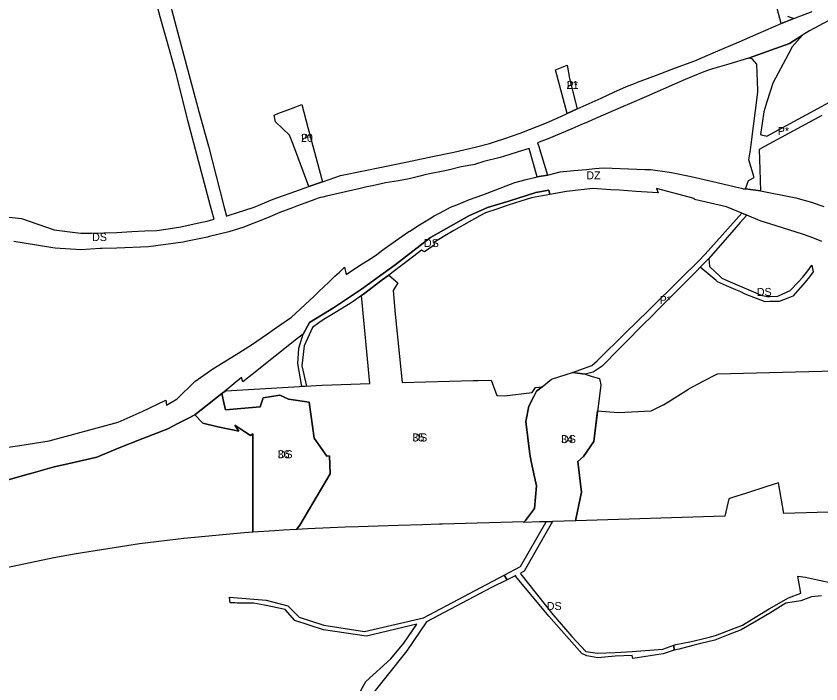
# Model space of a CAD drawing. Extents: x -501732 to -497665, y -1142022 to -1138283.
# Drawn here: x -499525 to -498822, y -1140888 to -1140303 of the extents above; entities that cross this region are included whole.
import ezdxf

# ---------------------------------------------------------------- set-up
doc = ezdxf.new("R2010")
doc.units = 0
for name, color, linetype in [('4', 7, 'Continuous'), ('43', 7, 'Continuous'), ('44', 7, 'Continuous'), ('5', 7, 'Continuous'), ('61', 7, 'Continuous'), ('7', 7, 'Continuous')]:
    doc.layers.add(name, color=color, linetype=linetype)

msp = doc.modelspace()

# ---------------------------------------------------------------- linework, layer by layer
at = {"layer": '4'}
for points in [[(-499533.86, -1140478.84), (-499520.59, -1140480.42), (-499492.05, -1140490.24), (-499471.17, -1140493.01), (-499468.63, -1140493.35), (-499459.42, -1140493.11), (-499448.67, -1140492.82), (-499437.1, -1140492.61), (-499424.11, -1140491.92), (-499412.75, -1140491.32), (-499402.08, -1140490.76), (-499392.35, -1140489.33), (-499381.33, -1140487.71), (-499369.64, -1140485.14), (-499357.43, -1140482.45), (-499354.19, -1140481.62), (-499352.11, -1140481.09), (-499355.18, -1140469.543), (-499375.07, -1140394.73), (-499384.85, -1140355.82), (-499390.45, -1140334.96), (-499399.25, -1140304.07), (-499413.21, -1140251.05)], [(-499391.39, -1140289.65), (-499381.85, -1140325.93), (-499365.33, -1140386.89), (-499357.13, -1140417.19), (-499343.61, -1140469.6), (-499341.31, -1140478.34), (-499339.68, -1140477.92), (-499317.1, -1140470.61), (-499300.46, -1140463.58), (-499281.61, -1140456.77), (-499269.37, -1140452.35), (-499266.71, -1140451.48), (-499264.81, -1140450.86), (-499263.54, -1140450.42), (-499257.33, -1140448.28), (-499256.34, -1140447.94), (-499241.58, -1140442.84), (-499221.53, -1140438.73), (-499204.27, -1140435.21), (-499202.74, -1140434.9), (-499184.51, -1140431.25), (-499165.12, -1140427.13), (-499161.13, -1140426.28), (-499142.43, -1140422.43), (-499123.87, -1140417.86), (-499111.16, -1140414.8), (-499105.974, -1140413.043), (-499097.94, -1140410.32), (-499084.44, -1140405.81), (-499061.44, -1140396.85), (-499048.96, -1140391.13), (-499043.27, -1140388.5), (-499034.63, -1140384.57), (-499013.75, -1140375), (-499002.59, -1140369.89), (-498991.5, -1140364.81), (-498984.65, -1140362.16), (-498981.92, -1140361.11), (-498965.17, -1140354.88), (-498948.6, -1140348.71), (-498931.83, -1140342.49), (-498913.6, -1140334.63), (-498892.94, -1140325.78), (-498876.36, -1140318.59), (-498856.22, -1140309.93), (-498852.4, -1140308.48), (-498845.2, -1140305.46), (-498829.21, -1140299.26)], [(-498815.24, -1140307.37), (-498831.5, -1140316.35), (-498835.82, -1140318.73), (-498837.51, -1140319.95), (-498849.08, -1140327.24), (-498884.91, -1140340.06), (-498901.89, -1140345.34), (-498916.42, -1140349.39), (-498919.84, -1140350.56), (-498923.98, -1140351.97), (-498928.75, -1140354.01), (-498940.1, -1140358.86), (-498949.62, -1140363), (-498959.42, -1140367.18), (-498973.97, -1140373.54), (-498988.97, -1140379.94), (-498994.37, -1140382.35), (-499018.51, -1140392.91), (-499025.04, -1140395.74), (-499031.55, -1140398.55), (-499039.4, -1140401.93), (-499059.29, -1140410.28), (-499069.33, -1140414.16), (-499069.02, -1140415.15), (-499068.57, -1140416.62), (-499060.61, -1140442.4), (-499069.49, -1140443.83), (-499076.68, -1140419.16), (-499086.13, -1140422.11), (-499094.46, -1140424.71), (-499102.1, -1140427.1), (-499116.22, -1140430.62), (-499123.5, -1140432.96), (-499124.06, -1140433.14), (-499135.95, -1140435.12), (-499147.59, -1140438.06), (-499153.2, -1140439.37), (-499162.17, -1140441.11), (-499167.85, -1140442.22), (-499172.15, -1140443.33), (-499181.49, -1140445.74), (-499190.84, -1140447.37), (-499202.11, -1140449.32), (-499213.64, -1140451.77), (-499218.43, -1140452.79), (-499224.48, -1140454.07), (-499237.22, -1140457.01), (-499253.91, -1140460.9), (-499256.93, -1140461.6), (-499259, -1140462.08), (-499261.13, -1140462.58), (-499264.09, -1140463.7), (-499272.833, -1140467.006), (-499279.11, -1140469.38), (-499283.56, -1140471.07), (-499294.72, -1140475.29), (-499303.43, -1140478.89), (-499312.68, -1140482.72), (-499319.8, -1140485.44), (-499326.12, -1140487.86), (-499339.19, -1140492.06), (-499356.17, -1140496.24), (-499357.15, -1140496.44), (-499357.988, -1140496.615), (-499376.73, -1140500.52), (-499379.3, -1140501.05), (-499403.15, -1140504.27), (-499409.47, -1140505.06), (-499437.13, -1140506.39), (-499450.1, -1140506.6), (-499451.64, -1140506.71), (-499468.57, -1140507.86), (-499491.14, -1140506.29), (-499493.22, -1140506.15), (-499496.6, -1140505.58), (-499527.13, -1140500.39)]]:
    msp.add_lwpolyline(points, dxfattribs=at)
for points in [[(-499159.55, -1140503.7), (-499168.02, -1140509.43), (-499170.64, -1140508.17), (-499177.54, -1140513.37), (-499189.52, -1140522.4), (-499199.435, -1140529.871), (-499200.19, -1140530.44), (-499205.05, -1140534.1), (-499209.99, -1140537.82), (-499220.46, -1140545.72), (-499223.155, -1140547.686), (-499230.66, -1140553.16), (-499233.16, -1140554.69), (-499236.04, -1140556.46), (-499241.25, -1140559.66), (-499246.66, -1140562.99), (-499251.02, -1140565.67), (-499255.78, -1140568.6), (-499260.6, -1140571.56), (-499266.099, -1140575.67), (-499273.423, -1140591.91), (-499275.476, -1140609.215), (-499271.445, -1140627.037), (-499275.262, -1140627.268), (-499278.996, -1140607.162), (-499278.116, -1140593.963), (-499274.18, -1140581.709), (-499268.73, -1140571.377), (-499247.611, -1140558.471), (-499223.265, -1140542.339), (-499193.933, -1140520.926), (-499162.842, -1140497.167), (-499129.403, -1140478.102), (-499112.977, -1140470.769), (-499093.618, -1140464.902), (-499070.739, -1140457.569), (-499059.3, -1140455.516), (-499058.422, -1140459.318), (-499074.55, -1140462.3), (-499083.99, -1140465.33), (-499094.87, -1140468.82), (-499105.77, -1140472.44), (-499114.75, -1140475.43), (-499119.674, -1140478.143), (-499129.23, -1140483.41), (-499142.57, -1140490.76), (-499150.34, -1140495.5), (-499155.56, -1140498.69), (-499159.98, -1140501.39)], [(-498866.028, -1140548.575), (-498859.16, -1140548.39), (-498855.36, -1140546.65), (-498848.48, -1140543.51), (-498841.42, -1140536.07), (-498837.56, -1140532), (-498833.07, -1140526.12), (-498829.33, -1140521.23), (-498828.23, -1140527.09), (-498831.44, -1140531.44), (-498835.39, -1140536.01), (-498846.01, -1140548.29), (-498850.51, -1140550.01), (-498858.03, -1140552.89), (-498866.08, -1140553.12), (-498870.24, -1140553.24), (-498887.81, -1140546.48), (-498891.52, -1140544.61), (-498896.02, -1140542.85), (-498903.99, -1140539.28), (-498911.91, -1140535.74), (-498913.17, -1140534.68), (-498927.07, -1140523.04), (-498919.49, -1140515.35), (-498918.88, -1140522.32), (-498910.03, -1140530.82), (-498908.07, -1140532.7), (-498900.87, -1140535.83), (-498874.38, -1140547.33), (-498872.65, -1140547.69), (-498868.09, -1140548.63)], [(-499061.682, -1140745.688), (-499056.3, -1140745.482), (-499080.97, -1140788.98), (-499084.32, -1140790.665), (-499083.85, -1140791.45), (-499055.84, -1140826.78), (-499039.41, -1140846.13), (-499027.17, -1140859.16), (-499016.91, -1140860.81), (-499001.5, -1140859.99), (-498986.43, -1140859.19), (-498959.73, -1140857.26), (-498950.11, -1140853.73), (-498950.06, -1140853.98), (-498949.88, -1140858.17), (-498959.32, -1140861.25), (-498986.02, -1140865.45), (-498986.43, -1140862.59), (-499001.47, -1140863.31), (-499016.46, -1140864.79), (-499026.07, -1140862.91), (-499030.49, -1140860.96), (-499059.43, -1140828.31), (-499088.14, -1140793.58), (-499088.374, -1140792.704), (-499095.98, -1140796.53), (-499098.45, -1140792.47), (-499084.18, -1140784.93)]]:
    msp.add_lwpolyline(points, close=True, dxfattribs=at)
at = {"layer": '43'}
for points in [[(-498850.81, -1140303.29), (-498845.2, -1140305.46), (-498852.4, -1140308.48), (-498856.22, -1140309.93), (-498862.32, -1140286.49)], [(-498820.71, -1140390.17), (-498838.52, -1140399.91), (-498856.24, -1140409.61), (-498870.72, -1140417.49), (-498875.59, -1140420.12), (-498874.91, -1140437.43), (-498874.22, -1140456.1), (-498887.5, -1140454.53), (-498884.7, -1140447.25), (-498879.75, -1140444.45), (-498884.45, -1140429), (-498883.12, -1140420.33), (-498882.38, -1140415.55), (-498876.66, -1140369.91), (-498876.72, -1140368.25), (-498877.56, -1140345.24), (-498881.63, -1140340.74), (-498884.91, -1140340.06), (-498849.08, -1140327.24), (-498837.51, -1140319.95), (-498846.62, -1140330.16), (-498849.91, -1140336.39), (-498863.6, -1140362.01), (-498865.87, -1140369.32), (-498868.67, -1140378.34), (-498871.39, -1140387.11), (-498874.37, -1140406.98), (-498872.69, -1140407.39), (-498869.69, -1140408.13), (-498868.81, -1140408.5), (-498824.33, -1140384.17), (-498814.604, -1140378.848)], [(-499228.39, -1140901.93), (-499219.31, -1140885.35), (-499197.54, -1140865.53), (-499186.16, -1140851.8), (-499174.8, -1140835.2), (-499218.89, -1140845.72), (-499256.52, -1140840.37), (-499281.61, -1140832.2), (-499290.1, -1140822.45), (-499308.12, -1140818.62), (-499317.73, -1140817), (-499331.83, -1140816.86), (-499334.13, -1140816.64), (-499338.073, -1140816.542), (-499338.733, -1140811.777), (-499306.66, -1140814.44), (-499287.7, -1140819.38), (-499277.72, -1140829.32), (-499256.21, -1140836.16), (-499220.72, -1140841.83), (-499169.08, -1140829.79), (-499098.45, -1140792.47), (-499095.98, -1140796.53), (-499109.48, -1140803.35), (-499166.49, -1140833.21), (-499183.66, -1140858.73), (-499202.02, -1140881.64), (-499219.29, -1140903.33)], [(-498821.01, -1140810.62), (-498829.76, -1140811.43), (-498838.99, -1140814.99), (-498852.13, -1140816.9), (-498866.08, -1140825.62), (-498878.17, -1140832.7), (-498891.32, -1140840.4), (-498902.68, -1140844.57), (-498914.15, -1140849.26), (-498926.5, -1140852.34), (-498933.45, -1140854.08), (-498945.37, -1140857.05), (-498949.88, -1140858.17), (-498950.06, -1140853.98), (-498950.11, -1140853.73), (-498948.29, -1140853.13), (-498936.08, -1140850.74), (-498926.35, -1140848.37), (-498918.132, -1140846.27), (-498913.59, -1140845.11), (-498890.12, -1140836.06), (-498877.86, -1140828.7), (-498866.72, -1140822.01), (-498849.78, -1140812.26), (-498838.96, -1140808.18), (-498841.59, -1140793.2), (-498834.88, -1140794.09), (-498824.4, -1140796.44), (-498814.65, -1140798.62)]]:
    msp.add_lwpolyline(points, dxfattribs=at)
msp.add_lwpolyline([(-498886.41, -1140477.51), (-498892.11, -1140484.03), (-498897.65, -1140490.35), (-498903.45, -1140497), (-498919.49, -1140515.35), (-498927.07, -1140523.04), (-498930.07, -1140526.09), (-498940.88, -1140537.06), (-498943.89, -1140540.27), (-498964.35, -1140560.64), (-498969.111, -1140565.455), (-498977.406, -1140573.845), (-498992.42, -1140589.03), (-498998.186, -1140594.862), (-499012.69, -1140609.53), (-499020.77, -1140614.83), (-499027.65, -1140616.56), (-499038.79, -1140615.12), (-499021.68, -1140609.06), (-499017.3, -1140604.79), (-499006.42, -1140594.19), (-499002.704, -1140590.57), (-498993.59, -1140581.69), (-498981.52, -1140569.92), (-498981.287, -1140569.69), (-498973.181, -1140561.713), (-498968.23, -1140556.84), (-498960.62, -1140549.36), (-498955.93, -1140544.75), (-498943.82, -1140532.62), (-498928.68, -1140517.74), (-498922.6, -1140511.74), (-498890.8, -1140475.65)], close=True, dxfattribs=at)
at = {"layer": '44'}
for points in [[(-499034.63, -1140384.57), (-499043.27, -1140388.5), (-499053.52, -1140350.39), (-499043.471, -1140346.14), (-499041.31, -1140357.9)], [(-499257.33, -1140448.28), (-499263.54, -1140450.42), (-499264.81, -1140450.86), (-499266.71, -1140451.48), (-499269.37, -1140452.35), (-499283.36, -1140414.68), (-499286.12, -1140407.58), (-499298.55, -1140395.96), (-499299.63, -1140389.98), (-499296.256, -1140388.683), (-499284.466, -1140384.15), (-499275.31, -1140380.63), (-499270.08, -1140400.91)]]:
    msp.add_lwpolyline(points, close=True, dxfattribs=at)
at = {"layer": '5'}
for points in [[(-499193.743, -1140564.164), (-499187.593, -1140623.765), (-499125.613, -1140622.084), (-499121.498, -1140622.007), (-499109.83, -1140621.793), (-499104.775, -1140635.27), (-499098.12, -1140635.51), (-499073.93, -1140632.6), (-499071.1, -1140628.29), (-499065.36, -1140627.7), (-499070.17, -1140631.57), (-499072.58, -1140636.22), (-499076.87, -1140644.51), (-499079.52, -1140657.94), (-499076.12, -1140686.47), (-499074.73, -1140693.14), (-499071.93, -1140706.5), (-499070.28, -1140714.4), (-499071.9, -1140734.07), (-499076.35, -1140739.92), (-499079.831, -1140744.505), (-499080.879, -1140745.886), (-499152.805, -1140747.86), (-499154.982, -1140747.925), (-499169.782, -1140748.335), (-499191.197, -1140748.979), (-499226.049, -1140750.027), (-499237.616, -1140750.501), (-499270.129, -1140751.834), (-499280.121, -1140752.464), (-499277.06, -1140748.76), (-499250.63, -1140703.66), (-499251.1, -1140688), (-499253.41, -1140688.26), (-499264.63, -1140672.68), (-499268.97, -1140641.12), (-499287.15, -1140638.53), (-499294.64, -1140635.04), (-499309.22, -1140637.3), (-499311.8, -1140645.11), (-499342.17, -1140647.8), (-499343.34, -1140642.72), (-499345.45, -1140633.59), (-499343.452, -1140631.948), (-499341.787, -1140631.307), (-499257.506, -1140626.19), (-499215.96, -1140624.634), (-499223.15, -1140547.739), (-499223.155, -1140547.686), (-499220.46, -1140545.72), (-499209.99, -1140537.82), (-499205.05, -1140534.1), (-499200.19, -1140530.44), (-499199.435, -1140529.871), (-499191.53, -1140536.772), (-499195.631, -1140543.336)], [(-499067.685, -1140745.918), (-499081.3, -1140746.44), (-499080.879, -1140745.886), (-499079.831, -1140744.505), (-499076.35, -1140739.92), (-499071.9, -1140734.07), (-499070.28, -1140714.4), (-499071.93, -1140706.5), (-499074.73, -1140693.14), (-499076.12, -1140686.47), (-499079.52, -1140657.94), (-499076.87, -1140644.51), (-499072.58, -1140636.22), (-499070.17, -1140631.57), (-499065.36, -1140627.7), (-499056.95, -1140620.92), (-499050.8, -1140618.95), (-499038.79, -1140615.12), (-499027.65, -1140616.56), (-499021.444, -1140618.517), (-499015.06, -1140620.53), (-499014.095, -1140625.974), (-499020.1, -1140675.56), (-499029, -1140688.61), (-499033.93, -1140693.11), (-499030.81, -1140719.88), (-499035.84, -1140743.39), (-499035.689, -1140744.86), (-499056.3, -1140745.482), (-499061.682, -1140745.688)], [(-499343.34, -1140642.72), (-499342.17, -1140647.8), (-499311.8, -1140645.11), (-499309.22, -1140637.3), (-499294.64, -1140635.04), (-499287.15, -1140638.53), (-499268.97, -1140641.12), (-499264.63, -1140672.68), (-499253.41, -1140688.26), (-499251.1, -1140688), (-499250.63, -1140703.66), (-499277.06, -1140748.76), (-499280.121, -1140752.464), (-499291.492, -1140753.18), (-499299.376, -1140753.677), (-499318.205, -1140754.864), (-499318.17, -1140668.78), (-499320.15, -1140670.38), (-499325.18, -1140666.98), (-499333.87, -1140661.11), (-499330.61, -1140666.33), (-499336.17, -1140665.33), (-499348.98, -1140662.77), (-499361.92, -1140659.52), (-499368.85, -1140652.22), (-499345.45, -1140633.59)]]:
    msp.add_lwpolyline(points, close=True, dxfattribs=at)
for points in [[(-498795.52, -1140736.85), (-498853.837, -1140738.595), (-498858.59, -1140711.59), (-498868.78, -1140714.9), (-498886.5, -1140720.67), (-498899.62, -1140724.8), (-498901.91, -1140725.52), (-498905.517, -1140740.941), (-499035.689, -1140744.86), (-499035.84, -1140743.39), (-499030.81, -1140719.88), (-499033.93, -1140693.11), (-499029, -1140688.61), (-499020.1, -1140675.56), (-499016.846, -1140648.693), (-498998.708, -1140650.243), (-498969.961, -1140648.733), (-498959.33, -1140643.34), (-498959.23, -1140643.29), (-498937.32, -1140629.72), (-498937.03, -1140629.54), (-498924.99, -1140623.14), (-498911.97, -1140616.22), (-498763.779, -1140612.414)], [(-499535.12, -1140709.81), (-499517.78, -1140705), (-499510.437, -1140702.959), (-499491.91, -1140697.81), (-499477.31, -1140694.47), (-499455.81, -1140689.52), (-499454.65, -1140689.07), (-499435.14, -1140681), (-499414.46, -1140672.94), (-499392.67, -1140664.44), (-499383.82, -1140659.9), (-499375.03, -1140655.39), (-499368.85, -1140652.22), (-499361.92, -1140659.52), (-499348.98, -1140662.77), (-499336.17, -1140665.33), (-499330.61, -1140666.33), (-499333.87, -1140661.11), (-499325.18, -1140666.98), (-499320.15, -1140670.38), (-499318.17, -1140668.78), (-499318.205, -1140754.864), (-499325.955, -1140755.459), (-499378.578, -1140760.25), (-499417.449, -1140765.058), (-499472.628, -1140773.759), (-499492.357, -1140777.353), (-499631.938, -1140806.639)]]:
    msp.add_lwpolyline(points, dxfattribs=at)
at = {"layer": '7'}
for points in [[(-499544.389, -1140682.197), (-499522.13, -1140678.98), (-499496.46, -1140674.88), (-499436.01, -1140658.54), (-499414.88, -1140649.23), (-499394.39, -1140639.31), (-499393.83, -1140643.64), (-499384.44, -1140638.12), (-499369.03, -1140623.13), (-499353.36, -1140611.94), (-499332.72, -1140599.3), (-499319.49, -1140590.99), (-499305.3, -1140581.24), (-499299.18, -1140577), (-499284.35, -1140566.74), (-499264.74, -1140548.21), (-499260.52, -1140544.22), (-499256.21, -1140540.15), (-499251.91, -1140536.09), (-499247.02, -1140531.47), (-499246.503, -1140530.982), (-499242.61, -1140527.31), (-499240.05, -1140524.89), (-499238.13, -1140523.07), (-499236.56, -1140529.54), (-499224.92, -1140521.41), (-499214.37, -1140515.05), (-499209.9, -1140511.8), (-499204.53, -1140507.91), (-499193.4, -1140499.9), (-499181.79, -1140491.83), (-499180.97, -1140491.41), (-499172.47, -1140486.08), (-499163.88, -1140480.68), (-499159.69, -1140478.05), (-499154.57, -1140475.35), (-499145.38, -1140470.51), (-499139.78, -1140468.59), (-499128.92, -1140463.74), (-499117.22, -1140459.66), (-499109.5, -1140456.67), (-499089.24, -1140448.82), (-499079.35, -1140446.36), (-499069.49, -1140443.83), (-499060.61, -1140442.4), (-499049.56, -1140439.55), (-499037.54, -1140438.44), (-499026.4, -1140437.41), (-499019.11, -1140436.74), (-499011.51, -1140436.04), (-499003.91, -1140436.33), (-498989.78, -1140436.88), (-498975.27, -1140437.44), (-498970.44, -1140437.63), (-498953.963, -1140439.931), (-498952.04, -1140440.2), (-498934.94, -1140443.6), (-498912.23, -1140448.95), (-498896.07, -1140452.75), (-498890.86, -1140453.96), (-498889.38, -1140454.31), (-498887.5, -1140454.53), (-498874.22, -1140456.1), (-498843.31, -1140462.31), (-498828.89, -1140466.29), (-498823.28, -1140468.41), (-498818.81, -1140469.76)], [(-498820.56, -1140500.53), (-498829.89, -1140496.72), (-498830.92, -1140496.39), (-498838.59, -1140493.92), (-498865.311, -1140485.355), (-498874.5, -1140482.41), (-498886.41, -1140477.51), (-498890.8, -1140475.65), (-498904.11, -1140470.12), (-498932.03, -1140463.78), (-498932.31, -1140462.83), (-498965.33, -1140454.12), (-498963.85, -1140457.95), (-498968.84, -1140457.62), (-498983.13, -1140456.67), (-498997.71, -1140455.69), (-499005.24, -1140455.31), (-499013.17, -1140454.85), (-499020.89, -1140454.24), (-499044.1, -1140456.67), (-499058.422, -1140459.318), (-499059.3, -1140455.516), (-499070.739, -1140457.569), (-499093.618, -1140464.902), (-499112.977, -1140470.769), (-499129.403, -1140478.102), (-499162.842, -1140497.167), (-499193.933, -1140520.926), (-499223.265, -1140542.339), (-499247.611, -1140558.471), (-499268.73, -1140571.377), (-499274.18, -1140581.709), (-499281.18, -1140586.94), (-499296.07, -1140598.84), (-499301.26, -1140602.98), (-499314.65, -1140613.66), (-499326.87, -1140623.41), (-499328.15, -1140619.37), (-499343.452, -1140631.948), (-499345.45, -1140633.59), (-499368.85, -1140652.22), (-499375.03, -1140655.39), (-499383.82, -1140659.9), (-499392.67, -1140664.44), (-499414.46, -1140672.94), (-499435.14, -1140681), (-499454.65, -1140689.07), (-499455.81, -1140689.52), (-499477.31, -1140694.47), (-499491.91, -1140697.81), (-499510.437, -1140702.959), (-499517.78, -1140705), (-499535.12, -1140709.81)]]:
    msp.add_lwpolyline(points, dxfattribs=at)

# ---------------------------------------------------------------- texts
at = {"layer": '4'}
for p in [(-499458.823, -1140500.144), (-499168.624, -1140505.368), (-498877.565, -1140548.144), (-499061.223, -1140822.955)]:
    msp.add_text('DS', height=7, dxfattribs=at).set_placement(p)
at = {"layer": '43'}
msp.add_text('P*', height=7, rotation=359.497417, dxfattribs=at).set_placement((-498859.302, -1140407.319))
msp.add_text('P*', height=7, dxfattribs=at).set_placement((-498962.532, -1140555.096))
at = {"layer": '44'}
msp.add_text('P*', height=7, rotation=359.497419, dxfattribs=at).set_placement((-499043.884, -1140367.051))
msp.add_text('P*', height=7, dxfattribs=at).set_placement((-499276.146, -1140413.333))
at = {"layer": '5'}
for p in [(-499178.729, -1140675.486), (-499048.705, -1140676.879), (-499296.497, -1140690.147)]:
    msp.add_text('DS', height=7, dxfattribs=at).set_placement(p)
at = {"layer": '61'}
for s, p in [('21', (-499043.884, -1140367.05)), ('20', (-499276.146, -1140413.333)), ('35', (-499178.745, -1140675.486)), ('34', (-499048.722, -1140676.879)), ('36', (-499296.514, -1140690.147))]:
    msp.add_text(s, height=7, dxfattribs=at).set_placement(p)
at = {"layer": '7'}
msp.add_text('DZ', height=7, dxfattribs=at).set_placement((-499026.645, -1140446.139))

doc.saveas('drawing.dxf')
